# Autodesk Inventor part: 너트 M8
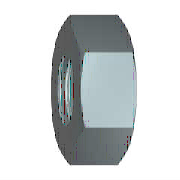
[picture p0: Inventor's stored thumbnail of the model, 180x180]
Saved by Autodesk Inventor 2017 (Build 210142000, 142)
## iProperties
IsCustomPart: 1
Created: 2012-02
Part Number: 너트 M8
Material: 강철, 연강
Description: 6각 너트 및 6각 가는 너트 - 이중 모따기
Document SubType Name: Modeling
Standard: KS B 1012
Designer: mduedu
Standards Organization: KS
Language: ko-KR
Size Designation: A M8
Categories: <MemberInstance><Categories><Category DisplayName="조임쇠" InternalName="e4da775c-781d-43d5-af7c-5136215cf5a6" Mnemonic="FSTN"><Category DisplayName="너트" InternalN
Density: 7.86 g/cm^3
Mass: 3.42669 g
Surface Area: 4.61759 cm^2
Volume: 0.435966 cm^3
Appearance: 강철
Author: mduedu
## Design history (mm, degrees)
sketch "스케치1"
  geometry: L1 (-7.506, 0)-(-3.753, 6.5); L2 (-3.753, 6.5)-(3.753, 6.5); L3 (3.753, 6.5)-(7.506, 0); L4 (7.506, 0)-(3.753, -6.5); L5 (3.753, -6.5)-(-3.753, -6.5); L6 (-3.753, -6.5)-(-7.506, 0); 2 further points
  constraints: 12 end point, 1 coincident, 1 horizontal, 11 other
  dimensions: "d0" = 15.01111 distance of L3.end L1.start (= 1.1547 x SW)
extrude "본체" new body sketch "스케치1" distance "d1" = 4 (= KOH); taper "d2" = 0 deg
sketch "스케치2"
  geometry: L1 (0, 3.753)-(0, 7.506) reference; L2 (0, 7.506)-(4, 7.506) reference; L3 (4, 3.753)-(4, 7.506) reference; L4 (-0.8, 0)-(4.8, 0) reference; L5 (0.581, 7.506)-(0, 6.5); L6 (3.419, 7.506)-(4, 6.5)
  constraints: 4 end point, 4 point on line
  dimensions: "d3" = 30 deg angle of L1 L5 (= ANG1); "d4" = 30 deg angle of L3 L6 (= ANG2); "d5" = 13 diameter of L5.end L4 (= SW0); "d6" = 13 diameter of L6.end L4 (= SW01)
revolve "모따기1" sketch "스케치2" stored, may be unused: angle "d7" = 90 deg
sketch "스케치3"
  geometry: A1 r 6.5 centre (0, 0) between (-3.25, -5.629) and (3.25, -5.629) reference; 1 further point
  constraints: 1 coincident
hole "스레드" sketch "스케치3" at (0, 0) diameter "d25" = 6.647; stored, may be unused: countersink angle "d29" = 82 deg, drill point angle "d31" = 118 deg; dims "d26" = 6, "d27" = 4, "d28" = 2, "d30" = 8
workaxis "Work Axis1"
workplane "Work Plane1"
body "Solid1"
chamfer "모따기2" distance "d8" = 0.67658 (= -0.5 x GD1 + 0.5 x NND); stored, may be unused: angle "d9" = 30 deg, second distance "d40" = 0.67658 (= -0.5 x GD1 + 0.5 x NND)
chamfer "모따기3" distance "d10" = 0.67658 (= -0.5 x GD1 + 0.5 x NND); stored, may be unused: angle "d11" = 30 deg, second distance "d41" = 0.67658 (= -0.5 x GD1 + 0.5 x NND)
other parameters: "ANG1" = 30 deg [user parameter; used in 1 equation term], "ANG2" = 30 deg [user parameter; used in 1 equation term], "NND" = 8 [user parameter; used in 4 equation terms], "KOH" = 4 [user parameter; used in 1 equation term], "SW" = 13 [user parameter; used in 4 equation terms], "SW0" = 13 (= SW) [user parameter; used in 1 equation term], "SW01" = 13 (= SW) [user parameter; used in 1 equation term], "GD1" = 6.64684 (computed from THREADDIA, PTC, TOA) [user parameter; used in 4 equation terms], "d13" = 0, "d14" = 0, "d39" = 0, "d42" = 0, "GUL" = 0.67658 (= 0.541266 x PTC) [user parameter], "TPU" = 8 (computed from PTC) [user parameter], "THREADDIA" = 8 [user parameter; used in 1 equation term], "TOA" = 30 deg [user parameter; used in 1 equation term], "PTC" = 1.25 [user parameter; used in 4 equation terms], "E0" = 15.015 (= 1.155 x SW) [user parameter], "GAL" = 0.67658 (= 0.541266 x PTC) [user parameter]
